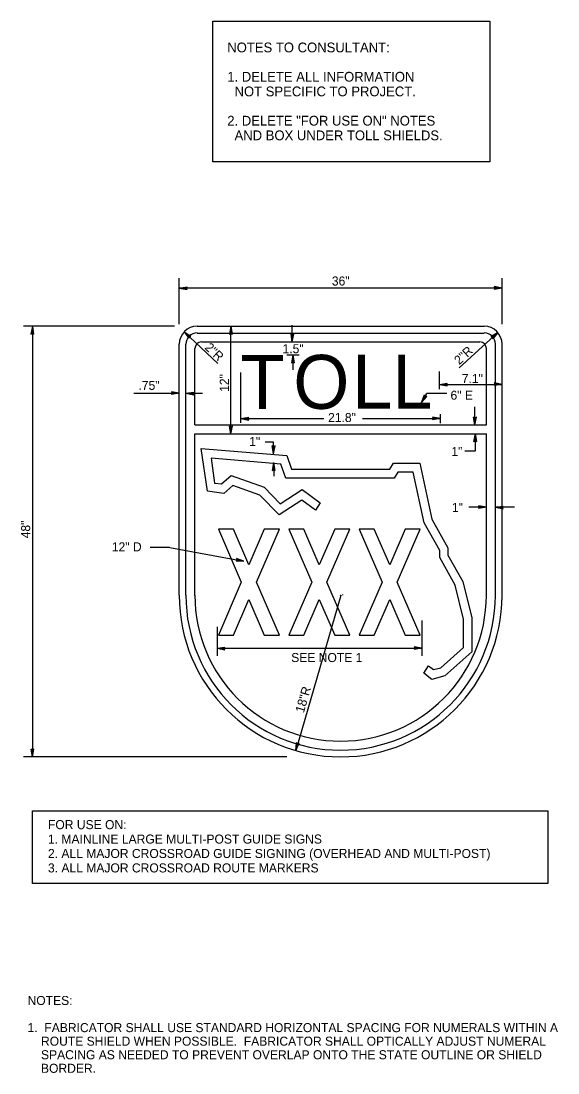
# Model space of a CAD drawing. Extents: x 52194 to 54069, y 8993 to 10161.
# Drawn here: x 52877 to 53376, y 9183 to 10161 of the extents above; entities that cross this region are included whole.
import ezdxf

# ---------------------------------------------------------------- set-up
doc = ezdxf.new("R2010")
doc.units = 0
for name, color, linetype in [('GSDims', 7, 'Continuous'), ('SignPanel', 7, 'Continuous'), ('TextAlert', 7, 'Continuous'), ('TextLabel', 7, 'Continuous'), ('TextNotes', 7, 'Continuous')]:
    doc.layers.add(name, color=color, linetype=linetype)

msp = doc.modelspace()

# ---------------------------------------------------------------- linework, layer by layer
at = {"layer": 'GSDims'}
for p, q in [((53023.82, 9879.03), (53023.82, 9921.63)), ((53323.82, 9879.03), (53323.82, 9921.63)), ((53023.82, 9912.43), (53031.12, 9913.53)), ((53023.82, 9912.43), (53030.82, 9912.93)), ((53023.82, 9912.43), (53031.12, 9911.03)), ((53023.82, 9912.43), (53030.82, 9911.63)), ((53323.82, 9912.43), (53023.82, 9912.43)), ((53030.62, 9912.33), (53031.12, 9913.53)), ((53031.12, 9911.03), (53030.62, 9912.33)), ((53323.82, 9912.43), (53316.52, 9913.83)), ((53316.52, 9913.83), (53317.02, 9912.53)), ((53317.02, 9912.53), (53316.52, 9911.23)), ((53323.82, 9912.43), (53316.52, 9911.23)), ((53323.82, 9912.43), (53316.82, 9913.13)), ((53323.82, 9912.43), (53316.82, 9911.93)), ((53019.42, 9877.03), (52879.12, 9877.03)), ((52887.22, 9877.03), (52885.82, 9869.73)), ((52885.82, 9869.73), (52887.12, 9870.23)), ((52887.22, 9877.03), (52886.42, 9870.03)), ((52887.12, 9870.23), (52888.32, 9869.73)), ((52887.22, 9877.03), (52888.32, 9869.73)), ((52887.22, 9877.03), (52887.72, 9870.03)), ((52887.22, 9877.03), (52887.22, 9477.03)), ((52923.72, 9877.03), (52923.72, 9877.03)), ((53028.42, 9871.88), (53059.72, 9842.43)), ((53028.42, 9871.88), (53034.52, 9867.68)), ((53028.42, 9871.88), (53032.72, 9865.88)), ((53028.42, 9871.88), (53033.02, 9866.58)), ((53028.42, 9871.88), (53033.92, 9867.38)), ((53071.82, 9877.03), (53070.42, 9869.73)), ((53070.42, 9869.73), (53071.72, 9870.33)), ((53071.82, 9877.03), (53071.12, 9870.03)), ((53071.72, 9870.33), (53073.02, 9869.73)), ((53071.82, 9877.03), (53073.02, 9869.73)), ((53071.82, 9877.03), (53072.32, 9870.03)), ((53071.82, 9777.03), (53071.82, 9877.03)), ((53128.87, 9862.43), (53127.72, 9869.73)), ((53128.97, 9869.18), (53127.72, 9869.73)), ((53128.87, 9862.43), (53128.37, 9869.43)), ((53128.87, 9862.43), (53128.87, 9878.08)), ((53128.87, 9862.43), (53130.27, 9869.68)), ((53128.87, 9862.43), (53129.62, 9869.43)), ((53130.27, 9869.68), (53128.97, 9869.18)), ((53319.77, 9871.28), (53283.92, 9838.33)), ((53319.77, 9871.28), (53313.47, 9867.38)), ((53319.77, 9871.28), (53314.07, 9867.08)), ((53319.77, 9871.28), (53314.97, 9866.18)), ((53319.77, 9871.28), (53315.17, 9865.48)), ((53323.82, 9877.03), (53323.82, 9877.03)), ((53032.72, 9865.88), (53033.22, 9867.18)), ((53033.22, 9867.18), (53034.52, 9867.68)), ((53313.47, 9867.38), (53314.67, 9866.78)), ((53314.67, 9866.78), (53315.17, 9865.48)), ((53123.72, 9850.38), (53135.12, 9850.38)), ((53129.42, 9850.38), (53128.02, 9843.13)), ((53129.42, 9850.38), (53128.67, 9843.38)), ((53129.42, 9850.38), (53129.42, 9836.43)), ((53129.42, 9850.38), (53130.57, 9843.08)), ((53129.42, 9850.38), (53129.92, 9843.38)), ((53128.02, 9843.13), (53129.32, 9843.63)), ((53129.32, 9843.63), (53130.57, 9843.08)), ((53289.47, 9842.43), (53289.47, 9842.43)), ((53081.12, 9787.23), (53081.12, 9834.03)), ((53265.62, 9818.48), (53265.62, 9835.03)), ((53265.62, 9823.03), (53272.92, 9824.18)), ((53265.62, 9823.03), (53272.62, 9823.53)), ((53265.62, 9823.03), (53323.82, 9823.03)), ((53265.62, 9823.03), (53272.87, 9821.63)), ((53265.62, 9823.03), (53272.62, 9822.28)), ((53272.37, 9822.93), (53272.92, 9824.18)), ((53272.87, 9821.63), (53272.37, 9822.93)), ((53317.07, 9823.13), (53316.52, 9821.88)), ((53323.82, 9823.03), (53316.52, 9821.88)), ((53323.82, 9823.03), (53316.57, 9824.43)), ((53316.57, 9824.43), (53317.07, 9823.13)), ((53323.82, 9823.03), (53316.82, 9823.78)), ((53323.82, 9823.03), (53316.82, 9822.53)), ((52981.47, 9814.73), (53023.82, 9814.73)), ((53023.82, 9814.73), (53016.52, 9816.13)), ((53016.52, 9816.13), (53017.02, 9814.83)), ((53017.02, 9814.83), (53016.52, 9813.63)), ((53023.82, 9814.73), (53016.52, 9813.63)), ((53023.82, 9814.73), (53016.82, 9815.53)), ((53023.82, 9814.73), (53016.82, 9814.23)), ((53030.02, 9814.73), (53037.32, 9815.93)), ((53030.02, 9814.73), (53037.02, 9815.23)), ((53030.02, 9814.73), (53037.22, 9813.33)), ((53030.02, 9814.73), (53037.02, 9814.03)), ((53030.02, 9814.73), (53045.32, 9814.73)), ((53036.72, 9814.63), (53037.32, 9815.93)), ((53037.22, 9813.33), (53036.72, 9814.63)), ((53249.07, 9806.28), (53253.77, 9814.43)), ((53249.07, 9806.28), (53251.67, 9813.18)), ((53249.07, 9806.28), (53252.17, 9812.58)), ((53249.07, 9806.28), (53253.17, 9811.98)), ((53249.07, 9806.28), (53253.97, 9811.88)), ((53252.57, 9812.08), (53251.67, 9813.18)), ((53253.97, 9811.88), (53252.57, 9812.08)), ((53272.42, 9814.43), (53253.77, 9814.43)), ((53298.62, 9785.38), (53298.42, 9802.28)), ((53081.12, 9791.33), (53088.42, 9792.53)), ((53081.12, 9791.33), (53088.12, 9791.83)), ((53081.12, 9791.33), (53088.42, 9789.93)), ((53081.12, 9791.33), (53088.12, 9790.63)), ((53081.12, 9791.33), (53158.22, 9791.33)), ((53087.82, 9791.23), (53088.42, 9792.53)), ((53088.42, 9789.93), (53087.82, 9791.23)), ((53193.98, 9791.33), (53266.52, 9791.33)), ((53266.52, 9791.33), (53259.22, 9792.73)), ((53259.22, 9792.73), (53259.82, 9791.43)), ((53259.82, 9791.43), (53259.22, 9790.13)), ((53266.52, 9791.33), (53259.22, 9790.13)), ((53266.52, 9791.33), (53259.52, 9792.03)), ((53266.52, 9791.33), (53259.52, 9790.83)), ((53266.52, 9786.98), (53266.52, 9795.48)), ((53298.62, 9785.38), (53297.32, 9792.68)), ((53298.62, 9792.08), (53297.32, 9792.68)), ((53298.62, 9785.38), (53298.02, 9792.38)), ((53298.62, 9785.38), (53299.92, 9792.68)), ((53299.92, 9792.68), (53298.62, 9792.08)), ((53298.62, 9785.38), (53299.22, 9792.38)), ((53071.82, 9777.03), (53070.62, 9784.33)), ((53071.92, 9783.73), (53070.62, 9784.33)), ((53071.82, 9777.03), (53071.32, 9784.03)), ((53071.82, 9777.03), (53073.22, 9784.33)), ((53071.82, 9777.03), (53072.52, 9784.03)), ((53073.22, 9784.33), (53071.92, 9783.73)), ((53298.72, 9777.13), (53297.32, 9769.83)), ((53298.72, 9777.13), (53298.02, 9770.13)), ((53298.72, 9777.13), (53298.92, 9760.98)), ((53298.72, 9777.13), (53299.92, 9769.83)), ((53298.72, 9777.13), (53299.22, 9770.13)), ((53111.45, 9769.28), (53103.55, 9769.28)), ((53111.45, 9758.58), (53110.25, 9765.88)), ((53111.55, 9765.28), (53110.25, 9765.88)), ((53111.45, 9758.58), (53110.95, 9765.58)), ((53111.45, 9758.58), (53111.45, 9769.28)), ((53111.45, 9758.58), (53112.85, 9765.88)), ((53111.45, 9758.58), (53112.15, 9765.58)), ((53112.85, 9765.88), (53111.55, 9765.28)), ((53297.32, 9769.83), (53298.62, 9770.33)), ((53298.62, 9770.33), (53299.92, 9769.83)), ((53298.92, 9760.98), (53289.22, 9760.98)), ((53111.45, 9750.38), (53110.15, 9743.08)), ((53110.15, 9743.08), (53111.45, 9743.68)), ((53111.45, 9750.38), (53110.85, 9743.38)), ((53111.45, 9750.38), (53111.65, 9737.88)), ((53111.45, 9750.38), (53112.75, 9743.08)), ((53111.45, 9750.38), (53112.05, 9743.38)), ((53111.45, 9743.68), (53112.75, 9743.08)), ((53309.32, 9708.83), (53292.82, 9708.83)), ((53309.32, 9708.83), (53302.02, 9710.23)), ((53302.02, 9710.23), (53302.52, 9708.93)), ((53302.52, 9708.93), (53302.02, 9707.73)), ((53309.32, 9708.83), (53302.02, 9707.73)), ((53309.32, 9708.83), (53302.32, 9709.63)), ((53309.32, 9708.83), (53302.32, 9708.33)), ((53317.62, 9708.83), (53324.92, 9710.03)), ((53317.62, 9708.83), (53324.62, 9709.33)), ((53317.62, 9708.83), (53324.82, 9707.43)), ((53317.62, 9708.83), (53324.62, 9708.13)), ((53335.52, 9708.83), (53317.62, 9708.83)), ((53324.32, 9708.73), (53324.92, 9710.03)), ((53324.82, 9707.43), (53324.32, 9708.73)), ((53015.14, 9671.37), (52996.74, 9671.37)), ((53015.14, 9671.37), (53083.95, 9658.74)), ((53077.35, 9660.07), (53076.55, 9658.92)), ((53083.95, 9658.74), (53076.55, 9658.92)), ((53083.95, 9658.74), (53076.97, 9659.52)), ((53083.95, 9658.74), (53077.06, 9661.44)), ((53077.06, 9661.44), (53077.35, 9660.07)), ((53083.95, 9658.74), (53077.21, 9660.72)), ((53173.82, 9627.03), (53132.22, 9482.93)), ((53173.79, 9627.02), (53173.79, 9627.02)), ((53173.79, 9627.02), (53173.79, 9627.02)), ((53058.92, 9597.97), (53058.92, 9570.97)), ((53249.36, 9603.76), (53249.36, 9570.97)), ((53058.92, 9577.87), (53066.22, 9579.07)), ((53058.92, 9577.87), (53065.92, 9578.37)), ((53058.92, 9577.87), (53066.22, 9576.47)), ((53058.92, 9577.87), (53065.92, 9577.17)), ((53058.92, 9577.87), (53138.57, 9577.87)), ((53065.62, 9577.77), (53066.22, 9579.07)), ((53066.22, 9576.47), (53065.62, 9577.77)), ((53138.57, 9577.87), (53249.36, 9577.87)), ((53249.36, 9577.87), (53242.06, 9579.27)), ((53242.06, 9579.27), (53242.66, 9577.97)), ((53242.66, 9577.97), (53242.06, 9576.67)), ((53249.36, 9577.87), (53242.06, 9576.67)), ((53249.36, 9577.87), (53242.36, 9578.57)), ((53249.36, 9577.87), (53242.36, 9577.37)), ((53132.22, 9482.93), (53132.87, 9490.28)), ((53132.22, 9482.93), (53133.47, 9489.88)), ((53132.22, 9482.93), (53135.37, 9489.63)), ((53132.22, 9482.93), (53134.67, 9489.53)), ((53132.87, 9490.28), (53134.02, 9489.43)), ((53134.02, 9489.43), (53135.37, 9489.63)), ((52887.22, 9477.03), (52886.02, 9484.33)), ((52887.32, 9483.73), (52886.02, 9484.33)), ((52887.22, 9477.03), (52886.72, 9484.03)), ((52887.22, 9477.03), (52888.62, 9484.33)), ((52887.22, 9477.03), (52887.92, 9484.03)), ((52888.62, 9484.33), (52887.32, 9483.73)), ((53123.62, 9477.03), (52879.12, 9477.03))]:
    msp.add_line(p, q, dxfattribs=at)
for radius in [0.141, 0.141, 0.0707]:
    msp.add_circle((53173.79, 9627.07), radius, dxfattribs=at)
at = {"layer": 'SignPanel'}
for p, q in [((53040.47, 9877.03), (53307.17, 9877.03)), ((53040.47, 9870.73), (53307.17, 9870.73)), ((53023.72, 9627.13), (53023.82, 9860.38)), ((53029.92, 9627.13), (53030.02, 9860.38)), ((53044.52, 9862.43), (53303.12, 9862.43)), ((53317.62, 9627.03), (53317.62, 9860.38)), ((53323.82, 9627.03), (53323.82, 9860.38)), ((53038.32, 9785.33), (53038.32, 9856.23)), ((53309.32, 9785.33), (53309.32, 9856.23)), ((53038.32, 9785.33), (53309.32, 9785.33)), ((53038.32, 9627.03), (53038.32, 9777.03)), ((53038.32, 9777.03), (53309.32, 9777.03)), ((53309.32, 9627.03), (53309.32, 9777.03)), ((53044.24, 9763.62), (53123.74, 9756.91)), ((53049.9, 9723.86), (53044.24, 9763.62)), ((53118.34, 9748.96), (53053.31, 9754.45)), ((53053.31, 9754.45), (53056.59, 9731.41)), ((53123.74, 9756.91), (53128.19, 9744.41)), ((53122.94, 9736.03), (53118.34, 9748.96)), ((53128.19, 9744.41), (53219.37, 9744.41)), ((53219.37, 9744.41), (53222.81, 9749.97)), ((53222.81, 9749.97), (53247.34, 9749.97)), ((53247.34, 9749.97), (53258.45, 9697.71)), ((53062.89, 9730.55), (53071.92, 9738.33)), ((53071.92, 9738.33), (53102.59, 9727.42)), ((53223.44, 9736.03), (53122.94, 9736.03)), ((53226.88, 9741.59), (53223.44, 9736.03)), ((53241.25, 9741.59), (53226.88, 9741.59)), ((53251.27, 9694.46), (53241.25, 9741.59)), ((53065.12, 9721.81), (53049.9, 9723.86)), ((53056.59, 9731.41), (53062.89, 9730.55)), ((53073.45, 9728.97), (53065.12, 9721.81)), ((53098.62, 9720.02), (53073.45, 9728.97)), ((53102.59, 9727.42), (53117.64, 9712.17)), ((53117.64, 9712.17), (53138.05, 9725.28)), ((53138.05, 9725.28), (53154.66, 9713)), ((53116.61, 9701.78), (53098.62, 9720.02)), ((53137.77, 9715.37), (53116.61, 9701.78)), ((53150.37, 9706.06), (53137.77, 9715.37)), ((53154.66, 9713), (53150.37, 9706.06)), ((53265.9, 9668.76), (53251.27, 9694.46)), ((53258.45, 9697.71), (53273.57, 9671.15)), ((53074.11, 9688.47), (53060.1, 9688.47)), ((53060.1, 9688.47), (53081.46, 9639.3)), ((53088.47, 9655.42), (53074.11, 9688.47)), ((53102.83, 9688.47), (53088.47, 9655.42)), ((53095.47, 9639.3), (53116.84, 9688.47)), ((53116.84, 9688.47), (53102.83, 9688.47)), ((53139.6, 9688.47), (53125.59, 9688.47)), ((53125.59, 9688.47), (53146.95, 9639.3)), ((53153.96, 9655.42), (53139.6, 9688.47)), ((53168.32, 9688.47), (53153.96, 9655.42)), ((53160.96, 9639.3), (53182.33, 9688.47)), ((53182.33, 9688.47), (53168.32, 9688.47)), ((53205.09, 9688.47), (53191.08, 9688.47)), ((53191.08, 9688.47), (53212.44, 9639.3)), ((53219.45, 9655.42), (53205.09, 9688.47)), ((53233.81, 9688.47), (53219.45, 9655.42)), ((53226.45, 9639.3), (53247.82, 9688.47)), ((53247.82, 9688.47), (53233.81, 9688.47)), ((53265.9, 9662.1), (53265.9, 9668.76)), ((53273.57, 9671.15), (53273.57, 9664.45)), ((53273.57, 9664.45), (53287.25, 9639.82)), ((53280.13, 9636.47), (53265.9, 9662.1)), ((53081.46, 9639.3), (53060.1, 9590.13)), ((53116.84, 9590.13), (53095.47, 9639.3)), ((53146.95, 9639.3), (53125.59, 9590.13)), ((53182.33, 9590.13), (53160.96, 9639.3)), ((53212.44, 9639.3), (53191.08, 9590.13)), ((53247.82, 9590.13), (53226.45, 9639.3)), ((53288, 9605.01), (53280.13, 9636.47)), ((53287.25, 9639.82), (53295.67, 9606.13)), ((53074.11, 9590.13), (53088.47, 9623.18)), ((53088.47, 9623.18), (53102.83, 9590.13)), ((53139.6, 9590.13), (53153.96, 9623.18)), ((53153.96, 9623.18), (53168.32, 9590.13)), ((53205.09, 9590.13), (53219.45, 9623.18)), ((53219.45, 9623.18), (53233.81, 9590.13)), ((53295.67, 9606.13), (53295.67, 9574.65)), ((53288, 9578.62), (53288, 9605.01)), ((53060.1, 9590.13), (53074.11, 9590.13)), ((53102.83, 9590.13), (53116.84, 9590.13)), ((53125.59, 9590.13), (53139.6, 9590.13)), ((53168.32, 9590.13), (53182.33, 9590.13)), ((53191.08, 9590.13), (53205.09, 9590.13)), ((53233.81, 9590.13), (53247.82, 9590.13)), ((53267.06, 9559.85), (53288, 9578.62)), ((53295.67, 9574.65), (53270.56, 9552.15)), ((53251.07, 9554.76), (53255.44, 9561.65)), ((53255.44, 9561.65), (53260.18, 9558.05)), ((53260.18, 9558.05), (53267.06, 9559.85)), ((53258.63, 9549.03), (53251.07, 9554.76)), ((53270.56, 9552.15), (53258.63, 9549.03))]:
    msp.add_line(p, q, dxfattribs=at)
for centre, radius, start, end in [((53040.48, 9860.37), 16.67, 90, 179.97628), ((53040.48, 9860.37), 10.47, 90, 179.97628), ((53307.15, 9860.37), 16.67, 0, 90), ((53307.15, 9860.37), 10.47, 0, 90), ((53044.52, 9856.23), 6.2, 90, 180), ((53303.12, 9856.23), 6.2, 0, 90), ((53173.77, 9627.08), 150.05, 179.98091, 359.98091), ((53173.77, 9627.08), 143.85, 179.98091, 359.98091), ((53173.77, 9627.08), 135.45, 179.98091, 359.98091)]:
    msp.add_arc(centre, radius, start, end, dxfattribs=at)
at = {"layer": 'TextAlert'}
msp.add_lwpolyline([(53055.1, 10160.55), (53312.61, 10160.55), (53312.61, 10029.83), (53055.1, 10029.83)], close=True, dxfattribs=at)
at = {"layer": 'TextLabel'}
msp.add_lwpolyline([(52887.22, 9427.03), (53366.42, 9427.03), (53366.42, 9359.4), (52887.22, 9359.4)], close=True, dxfattribs=at)

# ---------------------------------------------------------------- texts
at = {"layer": 'GSDims'}
for s, p in [('36"', (53165.6, 9914.86)), ('1.5"', (53119.8, 9851.98)), ('7.1"', (53286.39, 9824.28)), ('.75"', (52985.86, 9817.91)), ('6" E', (53275.91, 9808.78)), ('21.8"', (53162.11, 9788.05)), ('1"', (53088.78, 9765.72)), ('1"', (53276.71, 9756.48)), ('1"', (53277.27, 9704.6)), ('12" D', (52961.1, 9667.92)), ('SEE NOTE 1', (53127.82, 9565.11))]:
    msp.add_text(s, height=8.4, dxfattribs=at).set_placement(p)
for s, rotation, p in [('2"R', 316.51741, (53046.91, 9856.53)), ('2"R', 42.57524, (53284.01, 9840.73)), ('12"', 90, (53069.86, 9816.08)), ('48"', 90, (52885.21, 9680.03)), ('.', 90, (53176.29, 9625.92)), ('18"R', 73.85566, (53139.51, 9517.33))]:
    msp.add_text(s, height=8.4, rotation=rotation, dxfattribs=at).set_placement(p)
at = {"layer": 'SignPanel'}
for s, height, p in [('T', 50.08, (53080.71, 9800.18)), ('O', 50.08, (53129.81, 9800.33)), ('LL', 50.082, (53184.56, 9800.53))]:
    msp.add_text(s, height=height, dxfattribs=at).set_placement(p)
at = {"layer": 'TextAlert'}
for s, p in [('NOTES TO CONSULTANT:', (53068.42, 10131.48)), ('1. DELETE ALL INFORMATION', (53068.42, 10104.26)), ('  NOT SPECIFIC TO PROJECT.', (53068.42, 10090.65)), ('2. DELETE "FOR USE ON" NOTES', (53068.42, 10063.44)), ('  AND BOX UNDER TOLL SHIELDS.', (53068.42, 10049.83))]:
    msp.add_text(s, height=9.072, dxfattribs=at).set_placement(p)
at = {"layer": 'TextLabel'}
for s, p in [('FOR USE ON:', (52901.74, 9409.88)), ('1. MAINLINE LARGE MULTI-POST GUIDE SIGNS', (52901.74, 9396.48)), ('2. ALL MAJOR CROSSROAD GUIDE SIGNING (OVERHEAD AND MULTI-POST)', (52901.74, 9383.08)), ('3. ALL MAJOR CROSSROAD ROUTE MARKERS', (52901.74, 9369.68))]:
    msp.add_text(s, height=8.4, dxfattribs=at).set_placement(p)
at = {"layer": 'TextNotes'}
for s, p in [('NOTES:', (52882.76, 9246.53)), ('1.  FABRICATOR SHALL USE STANDARD HORIZONTAL SPACING FOR NUMERALS WITHIN A', (52882.76, 9221.33)), ('    ROUTE SHIELD WHEN POSSIBLE.  FABRICATOR SHALL OPTICALLY ADJUST NUMERAL', (52882.76, 9208.73)), ('    SPACING AS NEEDED TO PREVENT OVERLAP ONTO THE STATE OUTLINE OR SHIELD ', (52882.76, 9196.13)), ('    BORDER.', (52882.76, 9183.53))]:
    msp.add_text(s, height=8.4, dxfattribs=at).set_placement(p)

doc.saveas('drawing.dxf')
